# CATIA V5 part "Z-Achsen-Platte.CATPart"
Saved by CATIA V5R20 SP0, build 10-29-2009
Part number: Z-Achsen-Platte
Bounding box of the stored display mesh (mm): x 0 to 6, y -78 to 78, z -92 to 116
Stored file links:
  C:\Users\Andi\Desktop\Offene Projekte\Plasmacutter\Z-Achsen-Platte.CATPart
  C:\Program Files\Dassault Systemes\B20\win_b64\reffiles\standard\MetricThickPitch.txt
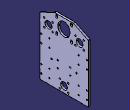
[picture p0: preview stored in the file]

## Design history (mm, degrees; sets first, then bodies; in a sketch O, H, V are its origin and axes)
Body1 (main body)
  Sketch1 on yz-plane, origin (0, 0, 0), H (0, 1, 0), V (0, 0, 1)
    line L1 (78, 92) -> (78, -92)
    line L2 (78, -92) -> (-78, -92)
    line L3 (-78, -92) -> (-78, 92)
    point P3 (-50, 72)
    construction line L4 (-30, 92) -> (-30, 52)
    construction line L5 (-30, 52) -> (-70, 52)
    construction line L6 (-70, 52) -> (-70, 92)
    construction line L7 (-70, 92) -> (-30, 92)
    point P8 (0, -72)
    construction line L8 (20, -52) -> (20, -92)
    construction line L9 (20, -92) -> (-20, -92)
    construction line L10 (-20, -92) -> (-20, -52)
    construction line L11 (-20, -52) -> (20, -52)
    point P13 (50, 72)
    construction line L12 (70, 92) -> (70, 52)
    construction line L13 (70, 52) -> (30, 52)
    construction line L14 (30, 52) -> (30, 92)
    construction line L15 (30, 92) -> (70, 92)
    construction circle A1 centre (-50, 72) radius 24
    construction circle A2 centre (-50, 72) radius 19.95
    construction circle A3 centre (0, -72) radius 19.95
    construction circle A4 centre (0, -72) radius 24
    construction line L16 (-48.596, 48) -> (42.4717, 48)
    circle A5 centre (-50, 72) radius 11
    circle A6 centre (50, 72) radius 11
    circle A7 centre (0, -72) radius 11
    point P20 (-29, 116)
    line L17 (-30, 116) -> (30, 116)
    construction line L18 (-29, 116) -> (29, 116)
    construction line L19 (29, 116) -> (29, 54)
    construction line L20 (29, 54) -> (-29, 54)
    construction line L21 (-29, 54) -> (-29, 116)
    construction line L22 (0, 83) -> (0, 87)
    point P24 (0, 83)
    point P25 (0, 87)
    line L23 (-19.1, 83) -> (-19.1, 87)
    line L24 (19.1, 87) -> (19.1, 83)
    arc A8 centre (0, 87) radius 19.1 from (-19.1, 87) to (19.1, 87) cw
    arc A9 centre (0, 83) radius 19.1 from (19.1, 83) to (-19.1, 83) cw
    line L25 (30.4396, 115.8982) -> (77.4396, 92.8982)
    line L26 (-30.4396, 115.8982) -> (-77.4396, 92.8982)
    arc A10 centre (-77, 92) radius 1 from (-77.4396, 92.8982) to (-78, 92) ccw
    point P32 (-77, 92)
    arc A11 centre (-30, 115) radius 1 from (-30.4396, 115.8982) to (-30, 116) cw
    point P35 (-30, 115)
    arc A12 centre (77, 92) radius 1 from (77.4396, 92.8982) to (78, 92) cw
    arc A13 centre (30, 115) radius 1 from (30.4396, 115.8982) to (30, 116) ccw
    point P41 (30, 115)
    distance L5 L7 = 40
    distance L4 L6 = 40
    distance L9 L11 = 40
    distance L8 L10 = 40
    distance L13 L15 = 40
    distance L12 L14 = 40
    radius A1 = 24
    radius A2 = 19.95
    radius A4 = 24 {= Sketch1.radius(A1)}
    radius A3 = 19.95 {= Sketch1.radius(A2)}
    distance L16 A4 = 96
    radius A5 = 11
    radius A7 = 11 {= Sketch1.radius(A5)}
    radius A6 = 11 {= Sketch1.radius(A5)}
    distance P13 P3 = 100
    distance L1 L3 = 156
    distance L2 P8 = 20
    distance L20 L17 = 62
    distance L20 P13 = 18
    distance L22 L23 = 19.1
    distance P24 L20 = 29 {= Sketch1.distance(P25 L17)}
    distance P25 L17 = 29
    distance L19 L21 = 58
    radius A10 = 1
    radius A11 = 1 {= Sketch1.radius(A10)}
    radius A12 = 1 {= Sketch1.radius(A10)}
    radius A13 = 1 {= Sketch1.radius(A10)}
    distance P35 P41 = 60
    distance P32 L17 = 24
    vertical: L1 V, L3 V, L4 V, L6 V, L8 V, L10 V, L12 V, L14 V, L19 V, L21 V, L22 V
    horizontal: L2 H, L5 H, L7 H, L9 H, L11 H, L13 H, L15 H, L16 H, L17 H, L18 H, L20 H
    equidistance: L1 L3 O, L4 L6 P3, L5 L7 P3, L8 L10 P8, L9 L11 P8, L12 L14 P13, L13 L15 P13
    coincidence: P8 V, P24 V, P20 L17
    tangency: L16 A1, A8 L23, A9 L23, A8 L24, A9 L24, A10 L26, A10 L3, A11 L26, A11 L17, A12 L25, A12 L1, A13 L25, A13 L17
    symmetry: P13 P3 V, L21 L19 V, L7 L2 H, L26 L25 L22
  Pad1: profile Sketch1, direction (1, 0, 0), length 6
  Sketch2 on end face of Pad1, origin (6, 0, 0), H (0, 1, 0), V (0, 0, 1)
    point P1 (-50, 72)
    construction line L1 (-36.5, 85.5) -> (-36.5, 58.5)
    construction line L2 (-36.5, 58.5) -> (-63.5, 58.5)
    construction line L3 (-63.5, 58.5) -> (-63.5, 85.5)
    construction line L4 (-63.5, 85.5) -> (-36.5, 85.5)
    point P6 (0, -72)
    construction line L5 (13.5, -58.5) -> (13.5, -85.5)
    construction line L6 (13.5, -85.5) -> (-13.5, -85.5)
    construction line L7 (-13.5, -85.5) -> (-13.5, -58.5)
    construction line L8 (-13.5, -58.5) -> (13.5, -58.5)
    reference projected point E1 (0, -72) from axis of face of Pad1 from Sketch1.A7
    circle A1 centre (-13.5, -58.5) radius 2.65
    circle A2 centre (-13.5, -85.5) radius 2.65
    circle A3 centre (13.5, -58.5) radius 2.65
    circle A4 centre (13.5, -85.5) radius 2.65
    point P11 (16.0118, -79.15)
    circle A5 centre (-63.5, 85.5) radius 2.65
    circle A6 centre (-36.5, 85.5) radius 2.65
    circle A7 centre (-36.5, 58.5) radius 2.65
    circle A8 centre (-63.5, 58.5) radius 2.65
    circle A9 centre (36.5, 85.5) radius 2.65
    circle A10 centre (63.5, 85.5) radius 2.65
    circle A11 centre (63.5, 58.5) radius 2.65
    circle A12 centre (36.5, 58.5) radius 2.65
    reference projected point E2 (-50, 72) from axis of face of Pad1 from Sketch1.A5
    distance L2 L4 = 27
    distance L1 L3 = 27
    distance L6 L8 = 27
    distance L5 L7 = 27
    radius A5 = 2.65
    radius A8 = 2.65 {= Sketch2.radius(A5)}
    radius A7 = 2.65 {= Sketch2.radius(A5)}
    radius A6 = 2.65 {= Sketch2.radius(A5)}
    radius A1 = 2.65 {= Sketch2.radius(A5)}
    radius A2 = 2.65 {= Sketch2.radius(A5)}
    vertical: L1 V, L3 V, L5 V, L7 V
    horizontal: L2 H, L4 H, L6 H, L8 H
    equidistance: L1 L3 P1, L2 L4 P1, L5 L7 P6, L6 L8 P6
    coincidence: P6 V, P6 E1, P1 E2
    symmetry: A6 A9 V, A12 A7 V, A11 A8 V, A10 A5 V, A1 A3 V, A4 A2 V
  Pocket1: profile Sketch2, direction (-1, 0, 0), through (limit type 6)
  Fillet1: radius 1, on edge [face of Pad1 from Sketch1.L1 | face of Pad1 from Sketch1.L2]; edge [face of Pad1 from Sketch1.L2 | face of Pad1 from Sketch1.L3]
  Sketch3 on end face of Pad1, origin (6, 0, 0), H (0, 1, 0), V (0, 0, 1)
    construction line L1 (-23.57, 110.57) -> (-23.57, 106.57)
    point P1 (-23.57, 110.57)
    line L2 (-20.47, 110.57) -> (-20.47, 106.57)
    line L3 (-26.67, 106.57) -> (-26.67, 110.57)
    arc A1 centre (-23.57, 106.57) radius 3.1 from (-20.47, 106.57) to (-26.67, 106.57) cw
    arc A2 centre (-23.57, 110.57) radius 3.1 from (-26.67, 110.57) to (-20.47, 110.57) cw
    construction line L4 (0, 87) -> (11.2409, 87)
    point P7 (0, 87)
    construction line L5 (0, 87) -> (0, 91.6551)
    reference projected point E1 (0, 87) from axis of face of Pad1 from Sketch1.A8
    distance L1 L2 = 3.1
    distance L4 P1 = 23.57
    distance L1 L5 = 23.57 {= Sketch3.distance(L4 P1)}
    length L1 = 4
    vertical: L1 V, L5 V
    tangency: A1 L2, A2 L2, A1 L3, A2 L3
    coincidence: P7 V, P7 E1
    horizontal: L4 H
  Pocket2: profile Sketch3, direction (-1, 0, 0), through (limit type 6)
  RectPattern1: of Pocket2, direction 1 instances 2, spacing 47.14 {= Sketch3.distance(L4 P1)*2}, along end face of Pad1, direction 2 instances 2, spacing 47.14 {= Sketch3.distance(L4 P1)*2}, along end face of Pad1 reversed
  Sketch4 on end face of Pad1, origin (6, 0, 0), H (0, 1, 0), V (0, 0, 1)
    point P1 (0, -22)
    construction line L1 (25, -6) -> (25, -38)
    construction line L2 (25, -38) -> (-25, -38)
    construction line L3 (-25, -38) -> (-25, -6)
    construction line L4 (-25, -6) -> (25, -6)
    construction line L5 (20, -11) -> (20, -33)
    construction line L6 (20, -33) -> (-20, -33)
    construction line L7 (-20, -33) -> (-20, -11)
    construction line L8 (-20, -11) -> (20, -11)
    circle A1 centre (-20, -11) radius 2.15
    circle A2 centre (20, -11) radius 2.15
    circle A3 centre (20, -33) radius 2.15
    circle A4 centre (-20, -33) radius 2.15
    reference projected line E1 (-77, -92) -> (77, -92) from edge [face of Pad1 from Sketch1.L2 | end face of Pad1]
    distance L2 L4 = 32
    distance L1 L3 = 50
    distance L6 L8 = 22
    distance L5 L7 = 40
    radius A1 = 2.15
    radius A2 = 2.15 {= Sketch4.radius(A1)}
    radius A3 = 2.15 {= Sketch4.radius(A1)}
    radius A4 = 2.15 {= Sketch4.radius(A1)}
    distance L2 E1 = 54
    coincidence: P1 V
    vertical: L1 V, L3 V, L5 V, L7 V
    horizontal: L2 H, L4 H, L6 H, L8 H
    equidistance: L1 L3 P1, L2 L4 P1, L5 L7 P1, L6 L8 P1
  Pocket3: profile Sketch4, direction (-1, 0, 0), through (limit type 6), deactivated
  Sketch5 on end face of Pad1, origin (6, 0, 0), H (0, 1, 0), V (0, 0, 1)
    point P1 (-60, 23)
    construction line L1 (-47, 36) -> (-47, 10)
    construction line L2 (-47, 10) -> (-73, 10)
    construction line L3 (-73, 10) -> (-73, 36)
    construction line L4 (-73, 36) -> (-47, 36)
    point P5 (-73, 36)
    point P6 (60, 23)
    construction line L5 (73, 36) -> (73, 10)
    construction line L6 (73, 10) -> (47, 10)
    construction line L7 (47, 10) -> (47, 36)
    construction line L8 (47, 36) -> (73, 36)
    reference intersected line E1 through (0, 0) direction (0, 1) from zx-plane
    reference projected line E2 (77, 116) -> (-77, 116) from edge [face of Pad1 from Sketch1.L17 | end face of Pad1]
    point P11 (-60, -61)
    construction line L9 (-47, -48) -> (-47, -74)
    construction line L10 (-47, -74) -> (-73, -74)
    construction line L11 (-73, -74) -> (-73, -48)
    construction line L12 (-73, -48) -> (-47, -48)
    point P16 (60, -61)
    construction line L13 (73, -48) -> (73, -74)
    construction line L14 (73, -74) -> (47, -74)
    construction line L15 (47, -74) -> (47, -48)
    construction line L16 (47, -48) -> (73, -48)
    reference intersected line E3 through (0, 0) direction (0, 1) from zx-plane
    distance L2 L4 = 26
    distance L1 L3 = 26
    distance L6 L8 = 26 {= Sketch5.distance(L1 L3)}
    distance L5 L7 = 26 {= Sketch5.distance(L1 L3)}
    distance P1 V = 60
    distance L4 E2 = 80
    distance L10 L12 = 26 {= Sketch5.distance(L1 L3)}
    distance L9 L11 = 26 {= Sketch5.distance(L1 L3)}
    distance L14 L16 = 26 {= Sketch5.distance(L1 L3)}
    distance L13 L15 = 26 {= Sketch5.distance(L1 L3)}
    distance P11 E3 = 60 {= Sketch5.distance(P1 V)}
    distance P16 P6 = 84
    vertical: L1 V, L3 V, L5 V, L7 V, L9 V, L11 V, L13 V, L15 V
    horizontal: L2 H, L4 H, L6 H, L8 H, L10 H, L12 H, L14 H, L16 H
    equidistance: L1 L3 P1, L2 L4 P1, L5 L7 P6, L6 L8 P6, L9 L11 P11, L10 L12 P11, L13 L15 P16, L14 L16 P16
    symmetry: P1 P6 E1, P16 P11 V
  Sketch6 on start face of Pad1, origin (0, -73, 36), H (0, 1, 0), V (0, 0, -1)
    point P1 (0, 0)
    reference projected point E1 (0, 0) from Sketch5.P5
    coincidence: E1 P1
  Hole1: placed by Sketch6, at (0, -73, 36) direction (1, 0, 0), diameter 4.3, through (limit type 6), counterbore diameter 8, counterbore depth 4.5
  UserPattern1: of Hole1, copies 16, at the points of Sketch5
  Sketch7 on start face of Pad1, origin (0, 38.2977, -17.6436), H (0, 1, 0), V (0, 0, -1)
    point P1 (1.7023, -0.6436)
    reference intersected line E1 through (-38.2977, 0) direction (0, 1) from zx-plane
    reference projected line E2 (38.7023, -133.6436) -> (-115.2977, -133.6436) from edge [start face of Pad1 | face of Pad1 from Sketch1.L17]
    distance E1 P1 = 40
    distance P1 E2 = 133
  Hole2: placed by Sketch7, at (0, 40, -17) direction (1, 0, 0), diameter 4.917, through (limit type 6), threaded "M6", thread diameter 6, thread depth 6, pitch 1
  Mirror1: of Hole2, about zx-plane
  Sketch8 on start face of Pad1, origin (0, -19.0214, -30.6154), H (0, 1, 0), V (0, 0, -1)
    point P1 (-0.9786, 2.3846)
    reference intersected line E1 (-58.9786, 61.3846) -> (97.0214, 61.3846) from face of Pad1 from Sketch1.L2
    reference intersected line E2 through (19.0214, 0) direction (0, 1) from zx-plane
    distance P1 E1 = 59
    distance P1 E2 = 20
  Hole3: placed by Sketch8, at (0, -20, -33) direction (1, 0, 0), diameter 4.3, through (limit type 6), counterbore diameter 8, counterbore depth 4.5
  RectPattern2: of Hole3, direction 1 instances 2, spacing 40, along start face of Pad1, direction 2 instances 2, spacing 22, along start face of Pad1 reversed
